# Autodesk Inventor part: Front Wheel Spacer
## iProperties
Shininess: 77.0
Angle Display Precision: 2
Document Length Units: 11269
Document Angle Units: 11279
Document Time Units: 11290
Document Mass Units: 11283
Document Length Units Precision: 3
Document Angle Units Precision: 2
Compacted: True
Created: 2001-08
Part Number: Front Wheel Spacer
Document SubType Name: Modeling
Designer: Martin Budgell
Density: 0.0
Volumn: 0.0
Area: 0.0
PropertySet Name: Model Information
Control State: 0
Master: False
Checked Out: False
Author: Martin Budgell
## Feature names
1. Extrusion1
2. Chamfer1
